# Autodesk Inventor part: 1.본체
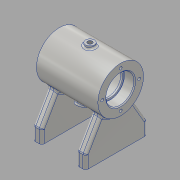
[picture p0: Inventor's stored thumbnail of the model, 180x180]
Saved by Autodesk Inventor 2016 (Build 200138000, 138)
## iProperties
Created: 2018-05
Part Number: 1.본체
Material: 알루미늄 6061
Document SubType Name: Modeling
Designer: 605-15
Density: 2.7 g/cm^3
Appearance: 알루미늄 - 평지
Mass: 317.681 g
Surface Area: 375.844 cm^2
Volume: 117.66 cm^3
Author: 605-15
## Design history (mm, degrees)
sketch "스케치1"
  geometry: L1 (-35, 0)-(35, 0); L2 (-35, 16)-(-35, 26); L3 (-35, 26)-(35, 26); L4 (35, 26)-(35, 16); L5 (35, 16)-(23, 16); L6 (23, 16)-(23, 14); L7 (23, 14)-(21, 14); L8 (21, 14)-(21, 21); L9 (21, 21)-(-21, 21); L10 (-21, 21)-(-21, 14); L11 (-21, 14)-(-23, 14); L12 (-23, 14)-(-23, 16); L13 (-23, 16)-(-35, 16); 1 further point
  constraints: 26 end point, 10 perpendicular, 3 point on line, 2 collinear, 2 vertical alignment, 1 horizontal, 1 midpoint, 1 vertical
  dimensions: "d0" = 70 distance of L1.start L1.end; "d1" = 35 distance of point (0, 0) L1.start; "d2" = 52 diameter of L3 L1; "d3" = 32 diameter of L5 L1; "d4" = 42 diameter of L9 L1; "d5" = 28 diameter of L7 L1; "d6" = 12 distance of L4.end L5.end; "d7" = 42 distance of L8.end L9.end
revolve "회전1" sketch "스케치1" stored, may be unused: angle "d8" = 90 deg
sketch "스케치2"
  geometry: L1 (-19.386, -17.325)-(-50, -35); L2 (-50, -35)-(-65, -35); L3 (-65, -35)-(-65, 35); L4 (-65, 35)-(-50, 35); L5 (-50, 35)-(-19.386, 17.325); A1 r 26 centre (0, 0) between (-19.386, -17.325) and (-19.386, 17.325) reference; 2 further points
  constraints: 10 end point, 2 perpendicular, 2 point on circle, 1 equal length, 1 horizontal, 1 horizontal alignment, 1 midpoint
  dimensions: "d9" = 30 deg angle of L4 L5; "d10" = 15 distance of L3.end L4.end; "d11" = 65 distance from line of point (0, 0) L3; "d12" = 70 distance between parallel lines of L2 L4; "d13" = 30 deg angle of L2 L1 (= d9)
extrude "돌출1" join sketch "스케치2" stored distance "d14" = 60; taper "d15" = 0 deg
sketch "스케치3"
  geometry: L1 (-19.386, 17.325)-(-50, 35) reference; L2 (-50, 35)-(-65, 35) reference; L3 (-65, 35)-(-65, -35) reference; L4 (-65, -35)-(-50, -35) reference; L5 (-50, -35)-(-19.386, -17.325) reference; A1 r 26 centre (0, 0) between (-19.386, 17.325) and (-19.386, -17.325) reference; 1 further point
extrude "돌출2" cut sketch "스케치3" stored distance "d16" = 40; taper "d17" = 0 deg
sketch "스케치4" dims "d18" = 42
  geometry: 3 further points
  constraints: 2 vertical alignment, 1 coincident, 2 other
hole "구멍1" sketch "스케치4" at (0, 21) diameter "d19" = 3.242; stored, may be unused: countersink angle "d23" = 90 deg, drill point angle "d25" = 118 deg; dims "d20" = 8, "d21" = 4, "d22" = 2, "d24" = 10
node "작업 평면1"
sketch "스케치5"
  geometry: C1 r 5 at (0, 0); 1 further point
  constraints: 1 centre point, 1 coincident
  dimensions: "d30" = 10 diameter of C1
extrude "돌출3" join sketch "스케치5" stored distance "d31" = 40; taper "d32" = 0 deg
sketch "스케치6"
  geometry: 1 further point
hole "구멍2" sketch "스케치6" at (0, 0) diameter "d33" = 5.188; stored, may be unused: countersink angle "d37" = 90 deg, drill point angle "d39" = 118 deg; dims "d34" = 16, "d35" = 4, "d36" = 2, "d38" = 16
sketch "스케치7"
  geometry: L1 (0, 0)-(-27.251, 9.919); L2 (0, 0)-(29, 0)
  constraints: 4 end point, 1 equal length, 1 horizontal
  dimensions: "d40" = 29 distance of L1.start L1.end; "d41" = 160 deg angle of L2 L1
node "작업 평면2"
sketch "스케치8"
  geometry: C1 r 6 at (0, 0); 1 further point
  constraints: 1 centre point, 1 coincident
  dimensions: "d42" = 12 diameter of C1
extrude "돌출4" join sketch "스케치8" stored distance "d43" = 40; taper "d44" = 0 deg
hole "구멍3" diameter "d47" = 5.188; stored, may be unused: countersink angle "d51" = 90 deg, drill point angle "d53" = 118 deg; dims "d45" = 10, "d46" = 10, "d48" = 16, "d49" = 4, "d50" = 2, "d52" = 16
sketch "스케치9"
  geometry: 5 further points
  constraints: 2 horizontal alignment, 2 vertical alignment
  dimensions: "d54" = 20 vertical distance of point (-30, 35) point (-5, 15); "d55" = 50 distance of point (-55, 15) point (-5, 15); "d56" = 25 horizontal distance of point (-30, 35) point (-5, 15); "d57" = 20 vertical distance of point (-5, 55) point (-30, 35)
hole "구멍4" sketch "스케치9" at (-5, 55), (-5, 15), (-55, 55), (-55, 15) diameter "d58" = 4.134; stored, may be unused: countersink angle "d62" = 90 deg, drill point angle "d64" = 118 deg; dims "d59" = 8, "d60" = 4, "d61" = 2, "d63" = 10
node "작업 평면3"
fillet "모깎기1" dims "d69" = 0.3
fillet "모깎기2" dims "d70" = 3
fillet "모깎기3" dims "d71" = 2
fillet "모깎기4" dims "d72" = 3
fillet "모깎기5" dims "d73" = 3
fillet "모깎기6" dims "d74" = 3
chamfer "모따기1" distance "d75" = 1; stored, may be unused: second distance "d76" = 2, angle "d77" = 45 deg
node "작업 평면4"
sketch "스케치11"
  geometry: L1 (-35, 26)-(-35, -26) reference; 2 further points
  constraints: 1 other
  dimensions: "d78" = 35 distance from line of L1 point (0, 0); "d79" = 26 vertical distance of L1.start point (0, 0)
feature "엠보싱2" sketch "스케치11" dims "d9" = 30 deg, "d10" = 15, "d11" = 65, "d12" = 70, "d13" = 30 deg (= d9), "d80" = 0.5, "d81" = 0
node "솔리드1"
pattern_circular "원형 패턴1" dims angle "d27" = 360 deg
mirror "대칭1"
node "투영된 루프1"
other parameters: "d29" = 29
